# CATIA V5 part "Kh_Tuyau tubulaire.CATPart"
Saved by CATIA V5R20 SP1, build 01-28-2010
Part number: Tuyau tubulaire
Bounding box of the stored display mesh (mm): x 0 to 1000, y -40 to 40, z -40 to 40
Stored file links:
  G:\Khaled_CFAO_2011\SIL\SIL_GR1\tmerino\Khaled\CAD_Thinkmotion\Kh_Tuyau tubulaire.CATPart
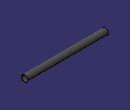
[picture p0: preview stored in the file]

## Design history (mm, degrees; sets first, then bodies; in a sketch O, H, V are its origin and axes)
Body1 (main body)
  Sketch1 on yz-plane, origin (0, 0, 0), H (0, 1, 0), V (0, 0, 1)
    circle A1 centre (0, 0) radius 40
    circle A2 centre (0, 0) radius 38
    radius A1 = 40
    radius A2 = 38
  Pad1: profile Sketch1, direction along X axis, length 1000
  Sketch2 on xy-plane, origin (0, 0, 0), H (1, 0, 0), V (0, 1, 0)
    line L1 (0, -40) -> (1000, -40)
    length L1 = 1000
    horizontal: L1 H
  Sketch3 on zx-plane, origin (0, 0, 0), H (-1, 0, 0), V (0, 0, 1)
    line L1 (0, -40) -> (-1000, -40)
    point P1 (0, -40)
    line L2 (0, 40) -> (-1000, 40)
    point P3 (0, 40)
    distance L2 L1 = 80
    length L1 = 1000
    length L2 = 1000
    coincidence: P1 V, P3 V
    horizontal: L1 H, L2 H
